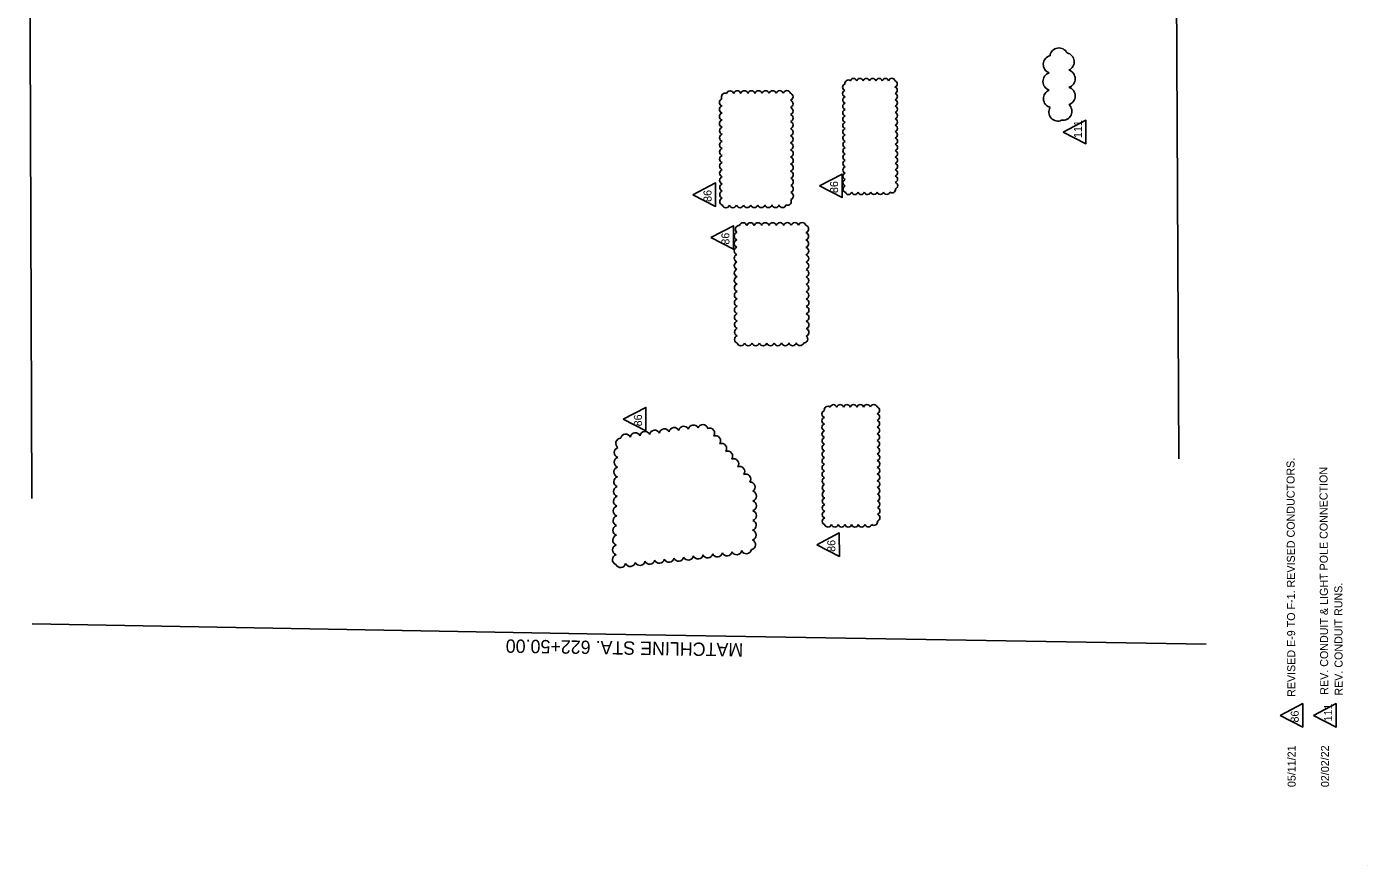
# Model space of a CAD drawing. Extents: x 928735 to 929560, y 637957 to 639219.
# Drawn here: x 928756 to 929560, y 637957 to 638460 of the extents above; entities that cross this region are included whole.
import ezdxf

# ---------------------------------------------------------------- set-up
doc = ezdxf.new("R2010")
doc.units = 0
for name, color, linetype in [('AdhocPoint_dp', 7, 'Continuous'), ('Cloud_dp', 7, 'Continuous'), ('MatchLines_dp', 7, 'Continuous')]:
    doc.layers.add(name, color=color, linetype=linetype)

msp = doc.modelspace()

# ---------------------------------------------------------------- linework, layer by layer
at = {"layer": 'AdhocPoint_dp'}
msp.add_line((929559.84, 637956.88), (929559.84, 637956.88), dxfattribs=at)
at = {"layer": 'Cloud_dp'}
for points in [[(929377.63, 638396.47), (929391.22, 638389.48), (929391.17, 638403.56)], [(929231.44, 638364.14), (929245.03, 638357.14), (929244.98, 638371.23)], [(929155.58, 638358.84), (929169.16, 638351.85), (929169.11, 638365.93)], [(929166.28, 638333.19), (929179.87, 638326.2), (929179.82, 638340.28)], [(929113.82, 638224.26), (929127.41, 638217.26), (929127.36, 638231.35)], [(929229.8, 638149.01), (929243.39, 638142.02), (929243.34, 638156.1)], [(929507.62, 638046.67), (929521.21, 638039.68), (929521.16, 638053.76)], [(929527.66, 638046.66), (929541.25, 638039.67), (929541.2, 638053.75)]]:
    msp.add_lwpolyline(points, close=True, dxfattribs=at)
for centre, radius, start, end in [((929371.05, 638437.03), 5.42, 104.8481, 249.8481), ((929375.02, 638441.49), 5.42, 26.70049, 171.70049), ((929378.76, 638438.61), 5.42, 293.26742, 78.26742), ((929379.3, 638428.45), 5.42, 287.77464, 72.77464), ((929247.33, 638423.34), 2, 107.69643, 252.69643), ((929248.67, 638425.71), 2, 48.35824, 193.35824), ((929251.9, 638426.61), 2, 17.69643, 162.69643), ((929255.72, 638426.62), 2, 17.69643, 162.69643), ((929259.54, 638426.63), 2, 17.69643, 162.69643), ((929263.35, 638426.65), 2, 17.69643, 162.69643), ((929267.17, 638426.66), 2, 17.69643, 162.69643), ((929270.98, 638426.67), 2, 17.69643, 162.69643), ((929274.8, 638426.69), 2, 17.69643, 162.69643), ((929276.11, 638425.38), 2, 287.69643, 72.69643), ((929370.84, 638426.77), 5.42, 107.76365, 252.76365), ((929174.87, 638417.58), 2.23, 66.84733, 211.84733), ((929177.88, 638418.97), 2.23, 17.69643, 162.69643), ((929182.13, 638418.98), 2.23, 17.69643, 162.69643), ((929186.38, 638419), 2.23, 17.69643, 162.69643), ((929190.63, 638419.01), 2.23, 17.69643, 162.69643), ((929194.88, 638419.03), 2.23, 17.69643, 162.69643), ((929199.13, 638419.04), 2.23, 17.69643, 162.69643), ((929203.38, 638419.06), 2.23, 17.69643, 162.69643), ((929207.63, 638419.07), 2.23, 17.69643, 162.69643), ((929211.88, 638419.08), 2.23, 17.69643, 162.69643), ((929213.34, 638417.63), 2.23, 287.69643, 72.69643), ((929247.34, 638419.53), 2, 107.69643, 252.69643), ((929247.36, 638415.71), 2, 107.69643, 252.69643), ((929276.12, 638421.57), 2, 287.69643, 72.69643), ((929276.13, 638417.75), 2, 287.69643, 72.69643), ((929371.12, 638416.51), 5.42, 110.37062, 255.37062), ((929379.34, 638418.11), 5.42, 287.69643, 72.69643), ((929173.66, 638414.29), 2.23, 107.69643, 252.69643), ((929173.67, 638410.03), 2.23, 107.69643, 252.69643), ((929213.35, 638413.38), 2.23, 287.69643, 72.69643), ((929213.37, 638409.13), 2.23, 287.69643, 72.69643), ((929247.37, 638411.89), 2, 107.69643, 252.69643), ((929247.38, 638408.08), 2, 107.69643, 252.69643), ((929276.15, 638413.94), 2, 287.69643, 72.69643), ((929276.16, 638410.12), 2, 287.69643, 72.69643), ((929374.41, 638408.49), 5.42, 149.33139, 294.33139), ((929377.34, 638408.93), 5.42, 262.68914, 47.68914), ((929173.69, 638405.78), 2.23, 107.69643, 252.69643), ((929173.7, 638401.53), 2.23, 107.69643, 252.69643), ((929213.38, 638404.88), 2.23, 287.69643, 72.69643), ((929213.4, 638400.63), 2.23, 287.69643, 72.69643), ((929247.4, 638404.26), 2, 107.69643, 252.69643), ((929247.41, 638400.45), 2, 107.69643, 252.69643), ((929276.17, 638406.31), 2, 287.69643, 72.69643), ((929276.19, 638402.49), 2, 287.69643, 72.69643), ((929276.2, 638398.68), 2, 287.69643, 72.69643), ((929173.72, 638397.28), 2.23, 107.69643, 252.69643), ((929173.73, 638393.03), 2.23, 107.69643, 252.69643), ((929213.41, 638396.38), 2.23, 287.69643, 72.69643), ((929213.43, 638392.13), 2.23, 287.69643, 72.69643), ((929247.42, 638396.63), 2, 107.69643, 252.69643), ((929247.44, 638392.82), 2, 107.69643, 252.69643), ((929276.21, 638394.86), 2, 287.69643, 72.69643), ((929276.23, 638391.04), 2, 287.69643, 72.69643), ((929173.74, 638388.78), 2.23, 107.69643, 252.69643), ((929173.76, 638384.53), 2.23, 107.69643, 252.69643), ((929213.44, 638387.88), 2.23, 287.69643, 72.69643), ((929213.45, 638383.63), 2.23, 287.69643, 72.69643), ((929247.45, 638389), 2, 107.69643, 252.69643), ((929247.46, 638385.19), 2, 107.69643, 252.69643), ((929276.24, 638387.23), 2, 287.69643, 72.69643), ((929276.25, 638383.41), 2, 287.69643, 72.69643), ((929173.77, 638380.28), 2.23, 107.69643, 252.69643), ((929173.79, 638376.03), 2.23, 107.69643, 252.69643), ((929213.47, 638379.38), 2.23, 287.69643, 72.69643), ((929213.48, 638375.13), 2.23, 287.69643, 72.69643), ((929247.47, 638381.37), 2, 107.69643, 252.69643), ((929247.49, 638377.56), 2, 107.69643, 252.69643), ((929276.27, 638379.6), 2, 287.69643, 72.69643), ((929276.28, 638375.78), 2, 287.69643, 72.69643), ((929173.8, 638371.78), 2.23, 107.69643, 252.69643), ((929173.82, 638367.53), 2.23, 107.69643, 252.69643), ((929213.5, 638370.88), 2.23, 287.69643, 72.69643), ((929213.51, 638366.63), 2.23, 287.69643, 72.69643), ((929247.5, 638373.74), 2, 107.69643, 252.69643), ((929247.51, 638369.92), 2, 107.69643, 252.69643), ((929276.29, 638371.97), 2, 287.69643, 72.69643), ((929276.3, 638368.15), 2, 287.69643, 72.69643), ((929173.83, 638363.28), 2.23, 107.69643, 252.69643), ((929173.85, 638359.03), 2.23, 107.69643, 252.69643), ((929213.53, 638362.38), 2.23, 287.69643, 72.69643), ((929213.54, 638358.13), 2.23, 287.69643, 72.69643), ((929247.53, 638366.11), 2, 107.69643, 252.69643), ((929247.54, 638362.29), 2, 107.69643, 252.69643), ((929248.85, 638360.99), 2, 197.69643, 342.69643), ((929252.67, 638361.01), 2, 197.69643, 342.69643), ((929256.48, 638361.02), 2, 197.69643, 342.69643), ((929260.3, 638361.03), 2, 197.69643, 342.69643), ((929264.11, 638361.04), 2, 197.69643, 342.69643), ((929267.93, 638361.06), 2, 197.69643, 342.69643), ((929271.74, 638361.07), 2, 197.69643, 342.69643), ((929274.98, 638361.97), 2, 228.35824, 13.35824), ((929276.32, 638364.34), 2, 287.69643, 72.69643), ((929173.86, 638354.78), 2.23, 107.69643, 252.69643), ((929175.32, 638353.33), 2.23, 197.69643, 342.69643), ((929179.57, 638353.34), 2.23, 197.69643, 342.69643), ((929183.82, 638353.36), 2.23, 197.69643, 342.69643), ((929188.07, 638353.37), 2.23, 197.69643, 342.69643), ((929192.32, 638353.39), 2.23, 197.69643, 342.69643), ((929196.57, 638353.4), 2.23, 197.69643, 342.69643), ((929200.82, 638353.42), 2.23, 197.69643, 342.69643), ((929205.07, 638353.43), 2.23, 197.69643, 342.69643), ((929209.32, 638353.45), 2.23, 197.69643, 342.69643), ((929212.33, 638354.83), 2.23, 246.84733, 31.84733), ((929182.61, 638334.1), 2.32, 107.69643, 252.69643), ((929183.33, 638338.13), 2.32, 87.03672, 232.03672), ((929185.67, 638339.76), 2.32, 17.69643, 162.69643), ((929190.09, 638339.78), 2.32, 17.69643, 162.69643), ((929194.52, 638339.79), 2.32, 17.69643, 162.69643), ((929198.95, 638339.81), 2.32, 17.69643, 162.69643), ((929203.38, 638339.82), 2.32, 17.69643, 162.69643), ((929207.8, 638339.84), 2.32, 17.69643, 162.69643), ((929212.23, 638339.85), 2.32, 17.69643, 162.69643), ((929216.66, 638339.87), 2.32, 17.69643, 162.69643), ((929221.08, 638339.88), 2.32, 17.69643, 162.69643), ((929222.6, 638338.37), 2.32, 287.69643, 72.69643), ((929222.62, 638333.94), 2.32, 287.69643, 72.69643), ((929182.63, 638329.67), 2.32, 107.69643, 252.69643), ((929222.63, 638329.52), 2.32, 287.69643, 72.69643), ((929182.64, 638325.24), 2.32, 107.69643, 252.69643), ((929182.66, 638320.81), 2.32, 107.69643, 252.69643), ((929222.65, 638325.09), 2.32, 287.69643, 72.69643), ((929222.67, 638320.66), 2.32, 287.69643, 72.69643), ((929182.67, 638316.39), 2.32, 107.69643, 252.69643), ((929182.69, 638311.96), 2.32, 107.69643, 252.69643), ((929222.68, 638316.24), 2.32, 287.69643, 72.69643), ((929222.7, 638311.81), 2.32, 287.69643, 72.69643), ((929182.7, 638307.53), 2.32, 107.69643, 252.69643), ((929182.72, 638303.11), 2.32, 107.69643, 252.69643), ((929222.71, 638307.38), 2.32, 287.69643, 72.69643), ((929222.73, 638302.96), 2.32, 287.69643, 72.69643), ((929182.73, 638298.68), 2.32, 107.69643, 252.69643), ((929182.75, 638294.25), 2.32, 107.69643, 252.69643), ((929222.74, 638298.53), 2.32, 287.69643, 72.69643), ((929222.76, 638294.1), 2.32, 287.69643, 72.69643), ((929182.76, 638289.83), 2.32, 107.69643, 252.69643), ((929222.77, 638289.67), 2.32, 287.69643, 72.69643), ((929182.78, 638285.4), 2.32, 107.69643, 252.69643), ((929182.79, 638280.97), 2.32, 107.69643, 252.69643), ((929222.79, 638285.25), 2.32, 287.69643, 72.69643), ((929222.8, 638280.82), 2.32, 287.69643, 72.69643), ((929182.81, 638276.54), 2.32, 107.69643, 252.69643), ((929182.82, 638272.12), 2.32, 107.69643, 252.69643), ((929222.1, 638272.35), 2.32, 267.03672, 52.03672), ((929222.82, 638276.39), 2.32, 287.69643, 72.69643), ((929184.34, 638270.61), 2.32, 197.69643, 342.69643), ((929188.77, 638270.62), 2.32, 197.69643, 342.69643), ((929193.2, 638270.64), 2.32, 197.69643, 342.69643), ((929197.63, 638270.65), 2.32, 197.69643, 342.69643), ((929202.05, 638270.67), 2.32, 197.69643, 342.69643), ((929206.48, 638270.68), 2.32, 197.69643, 342.69643), ((929210.91, 638270.7), 2.32, 197.69643, 342.69643), ((929215.33, 638270.71), 2.32, 197.69643, 342.69643), ((929219.76, 638270.73), 2.32, 197.69643, 342.69643), ((929236.42, 638229.95), 2.11, 49.00756, 194.00756), ((929239.82, 638230.91), 2.11, 17.69643, 162.69643), ((929243.84, 638230.93), 2.11, 17.69643, 162.69643), ((929247.86, 638230.94), 2.11, 17.69643, 162.69643), ((929251.88, 638230.96), 2.11, 17.69643, 162.69643), ((929255.91, 638230.97), 2.11, 17.69643, 162.69643), ((929259.93, 638230.98), 2.11, 17.69643, 162.69643), ((929263.95, 638231), 2.11, 17.69643, 162.69643), ((929265.33, 638229.62), 2.11, 287.69643, 72.69643), ((929235.02, 638227.43), 2.11, 107.69643, 252.69643), ((929235.03, 638223.41), 2.11, 107.69643, 252.69643), ((929265.35, 638225.6), 2.11, 287.69643, 72.69643), ((929265.36, 638221.58), 2.11, 287.69643, 72.69643), ((929121.12, 638213.1), 3.06, 25.1828, 170.1828), ((929126.9, 638213.88), 3.06, 25.1828, 170.1828), ((929132.69, 638214.66), 3.06, 25.1828, 170.1828), ((929138.48, 638215.44), 3.06, 25.1828, 170.1828), ((929144.26, 638216.22), 3.06, 25.1828, 170.1828), ((929150.05, 638217), 3.06, 25.1828, 170.1828), ((929155.84, 638217.78), 3.06, 25.1828, 170.1828), ((929161.48, 638218.01), 3.06, 14.56954, 159.56954), ((929165.52, 638215.92), 3.06, 325.62401, 110.62401), ((929235.05, 638219.39), 2.11, 107.69643, 252.69643), ((929235.06, 638215.36), 2.11, 107.69643, 252.69643), ((929265.37, 638217.56), 2.11, 287.69643, 72.69643), ((929112.34, 638209.78), 3.06, 90.49087, 235.49087), ((929115.33, 638212.32), 3.06, 25.1828, 170.1828), ((929169.12, 638211.33), 3.06, 325.62401, 110.62401), ((929172.73, 638206.73), 3.06, 325.62401, 110.62401), ((929235.07, 638211.34), 2.11, 107.69643, 252.69643), ((929235.09, 638207.32), 2.11, 107.69643, 252.69643), ((929265.39, 638213.54), 2.11, 287.69643, 72.69643), ((929265.4, 638209.51), 2.11, 287.69643, 72.69643), ((929111.37, 638198.48), 3.06, 106.48688, 251.48688), ((929111.47, 638204.32), 3.06, 106.48688, 251.48688), ((929176.33, 638202.14), 3.06, 325.62401, 110.62401), ((929179.94, 638197.54), 3.06, 325.62401, 110.62401), ((929235.1, 638203.3), 2.11, 107.69643, 252.69643), ((929235.11, 638199.28), 2.11, 107.69643, 252.69643), ((929265.41, 638205.49), 2.11, 287.69643, 72.69643), ((929265.43, 638201.47), 2.11, 287.69643, 72.69643), ((929111.27, 638192.64), 3.06, 106.48688, 251.48688), ((929183.54, 638192.95), 3.06, 325.62401, 110.62401), ((929235.13, 638195.25), 2.11, 107.69643, 252.69643), ((929235.14, 638191.23), 2.11, 107.69643, 252.69643), ((929265.44, 638197.45), 2.11, 287.69643, 72.69643), ((929265.46, 638193.42), 2.11, 287.69643, 72.69643), ((929111.06, 638180.96), 3.06, 106.48688, 251.48688), ((929111.16, 638186.8), 3.06, 106.48688, 251.48688), ((929187.15, 638188.36), 3.06, 325.62401, 110.62401), ((929189.75, 638183.57), 3.06, 306.53102, 91.53102), ((929235.16, 638187.21), 2.11, 107.69643, 252.69643), ((929235.17, 638183.19), 2.11, 107.69643, 252.69643), ((929265.47, 638189.4), 2.11, 287.69643, 72.69643), ((929265.48, 638185.38), 2.11, 287.69643, 72.69643), ((929110.96, 638175.13), 3.06, 106.48688, 251.48688), ((929190.63, 638178.2), 3.06, 287.00579, 72.00579), ((929235.18, 638179.16), 2.11, 107.69643, 252.69643), ((929235.2, 638175.14), 2.11, 107.69643, 252.69643), ((929265.5, 638181.36), 2.11, 287.69643, 72.69643), ((929265.51, 638177.34), 2.11, 287.69643, 72.69643), ((929110.85, 638169.29), 3.06, 106.48688, 251.48688), ((929190.53, 638166.52), 3.06, 287.00579, 72.00579), ((929190.58, 638172.36), 3.06, 287.00579, 72.00579), ((929235.21, 638171.12), 2.11, 107.69643, 252.69643), ((929235.22, 638167.1), 2.11, 107.69643, 252.69643), ((929265.52, 638173.31), 2.11, 287.69643, 72.69643), ((929265.54, 638169.29), 2.11, 287.69643, 72.69643), ((929110.65, 638157.61), 3.06, 106.48688, 251.48688), ((929110.75, 638163.45), 3.06, 106.48688, 251.48688), ((929190.48, 638160.68), 3.06, 287.00579, 72.00579), ((929235.24, 638163.08), 2.11, 107.69643, 252.69643), ((929236.62, 638161.7), 2.11, 197.69643, 342.69643), ((929240.64, 638161.72), 2.11, 197.69643, 342.69643), ((929244.66, 638161.73), 2.11, 197.69643, 342.69643), ((929248.69, 638161.74), 2.11, 197.69643, 342.69643), ((929252.71, 638161.76), 2.11, 197.69643, 342.69643), ((929256.73, 638161.77), 2.11, 197.69643, 342.69643), ((929260.75, 638161.79), 2.11, 197.69643, 342.69643), ((929264.15, 638162.75), 2.11, 229.00756, 14.00756), ((929265.55, 638165.27), 2.11, 287.69643, 72.69643), ((929110.54, 638151.77), 3.06, 106.48688, 251.48688), ((929190.06, 638149.13), 3.06, 280.6124, 65.6124), ((929190.43, 638154.84), 3.06, 287.00579, 72.00579), ((929110.44, 638145.94), 3.06, 106.48688, 251.48688), ((929164.4, 638144.16), 3.06, 203.76701, 348.76701), ((929170.21, 638144.8), 3.06, 203.76701, 348.76701), ((929176.01, 638145.44), 3.06, 203.76701, 348.76701), ((929181.82, 638146.08), 3.06, 203.76701, 348.76701), ((929187.62, 638146.71), 3.06, 203.76701, 348.76701), ((929110.34, 638140.1), 3.06, 106.48688, 251.48688), ((929112.17, 638138.43), 3.06, 203.76701, 348.76701), ((929117.97, 638139.07), 3.06, 203.76701, 348.76701), ((929123.78, 638139.7), 3.06, 203.76701, 348.76701), ((929129.58, 638140.34), 3.06, 203.76701, 348.76701), ((929135.38, 638140.98), 3.06, 203.76701, 348.76701), ((929141.19, 638141.61), 3.06, 203.76701, 348.76701), ((929146.99, 638142.25), 3.06, 203.76701, 348.76701), ((929152.8, 638142.89), 3.06, 203.76701, 348.76701), ((929158.6, 638143.53), 3.06, 203.76701, 348.76701)]:
    msp.add_arc(centre, radius, start, end, dxfattribs=at)
at = {"layer": 'MatchLines_dp'}
for points in [[(929443.52, 638998.1), (929444.75, 638641.91), (929446.91, 638200.47)], [(928756.17, 638974.21), (928757.64, 638618.14), (928759.14, 638176.75)], [(929463.31, 638089.34), (929103.36, 638095.32), (928759.39, 638101.7)]]:
    msp.add_lwpolyline(points, dxfattribs=at)

# ---------------------------------------------------------------- texts
at = {"layer": 'Cloud_dp'}
for s, p in [('111', (929388.8, 638392.88)), ('86', (929166.74, 638354.62)), ('86', (929242.61, 638359.92)), ('86', (929177.45, 638328.97)), ('86', (929124.99, 638220.03)), ('REVISED E-9 TO F-1. REVISED CONDUCTORS.', (929516.76, 638057.79)), ('REV. CONDUIT & LIGHT POLE CONNECTION', (929536.48, 638059.1)), ('86', (929240.96, 638144.79)), ('REV. CONDUIT RUNS.', (929545.14, 638058.53)), ('86', (929518.79, 638042.45)), ('111', (929538.82, 638043.07)), ('05/11/21', (929516.95, 638003.72)), ('02/02/22', (929536.99, 638003.71))]:
    msp.add_text(s, height=4.8, rotation=90.19643, dxfattribs=at).set_placement(p)
at = {"layer": 'MatchLines_dp'}
msp.add_text('MATCHLINE STA. 622+50.00', height=8, rotation=179.04782, dxfattribs=at).set_placement((929185.79, 638089.95))

doc.saveas('drawing.dxf')
